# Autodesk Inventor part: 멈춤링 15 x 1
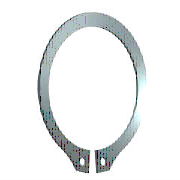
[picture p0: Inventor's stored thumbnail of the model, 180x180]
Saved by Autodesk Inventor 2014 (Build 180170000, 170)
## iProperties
IsCustomPart: 1
Created: 2012-02
Part Number: 멈춤링 15 x 1
Material: 강철, 연강
Description: 리테이닝 링(C형)
Document SubType Name: Modeling
Standard: KS B 1336
Designer: mduedu
Standards Organization: KS
Language: ko-KR
Size Designation: 15 x 1
Categories: <MemberInstance><Categories><Category DisplayName="샤프트 부품" InternalName="7f7aeb1f-a693-4053-b835-cee3144e0d98" Mnemonic="SHFT"><Category DisplayName="써클립" Inter
Density: 1 g/cm^3
Appearance: Blue - Wall Paint - Glossy
Author: mduedu
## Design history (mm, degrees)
sketch "스케치1"
  geometry: L1 (-6, 0)-(6, 0) reference; L2 (0, 20.189)-(0, -80.536) reference; L3 (-48.09, 0)-(48.09, 0) reference; L4 (-0.425, -14.637)-(-0.425, -18.137); L5 (-0.425, -6.54)-(-0.425, -13.29); L6 (-2.795, 2.1)-(3.672, 2.1); L7 (0.425, -6.54)-(0.425, -13.29); L8 (0.425, -14.637)-(0.425, -18.137); C1 r 0.85 at (-1.7, -16.283); C2 r 0.85 at (1.7, -16.283); A1 r 7.15 centre (0, -7.5) between (0.425, -14.637) and (-0.425, -14.637); A2 r 9.075 centre (0, -6.975) between (4.291, -14.971) and (-4.291, -14.971); A3 r 10.646 centre (0, -7.5) between (-2.023, -17.952) and (-0.425, -18.137); A4 r 1.7 centre (-1.7, -16.283) between (-3.397, -16.376) and (-2.023, -17.952); A5 r 1.7 centre (-5.095, -16.469) between (-3.397, -16.376) and (-4.291, -14.971); A6 r 1.7 centre (5.095, -16.469) between (4.291, -14.971) and (3.397, -16.376); A7 r 1.7 centre (1.7, -16.283) between (2.023, -17.952) and (3.397, -16.376); A8 r 10.646 centre (0, -7.5) between (0.425, -18.137) and (2.023, -17.952)
  constraints: 16 point on circle, 12 end point, 10 centre point, 9 symmetric about line, 5 point on line, 4 tangent, 3 coincident, 2 horizontal, 1 perpendicular, 1 vertical, 5 other
  dimensions: "d0" = 14.3 diameter of A1 (= ND); "d1" = 3.5 distance of L4.end L4.start (= SRB2); "d6" = 0.425 distance between parallel lines of L2 L5 (= 0.25 x SD5); "d7" = 2.1 distance between parallel lines of L6 L3 (= SRB1); "d8" = 0.525 distance of A1.centre A2.centre (= 0.25 x SRB1); "d9" = 1.7 radius of A4 (= SD5); "d10" = 1.7 radius of A5 (= SD5); "d11" = 1.275 distance from line of L4 A4.centre (= 0.75 x SD5); "d12" = 1.7 diameter of C1 (= SD5); "d13" = 1.7 diameter of C2 (= SD5); "d14" = 7.5 distance from line of A1.centre L1 (= 0.5 x WD)
extrude "본체" new body sketch "스케치1" distance "d2" = 1 (= SD); taper "d3" = 0 deg
workaxis "Work Axis1"
workplane "Work Plane1"
body "Solid1"
other parameters: "WD" = 15 (= WDMIN) [user parameter; used in 1 equation term], "SD" = 1 [user parameter; used in 1 equation term], "SRB1" = 2.1 [user parameter; used in 2 equation terms], "ND" = 14.3 [user parameter; used in 1 equation term], "SRB2" = 3.5 [user parameter; used in 1 equation term], "SD5" = 1.7 [user parameter; used in 6 equation terms], "d15" = 0, "d16" = 0, "d17" = 0, "d41" = 0, "d42" = 0, "WDMIN" = 15 [user parameter; used in 1 equation term], "SD3" = 13.8 [user parameter], "WDMAX" = 16 [user parameter]
